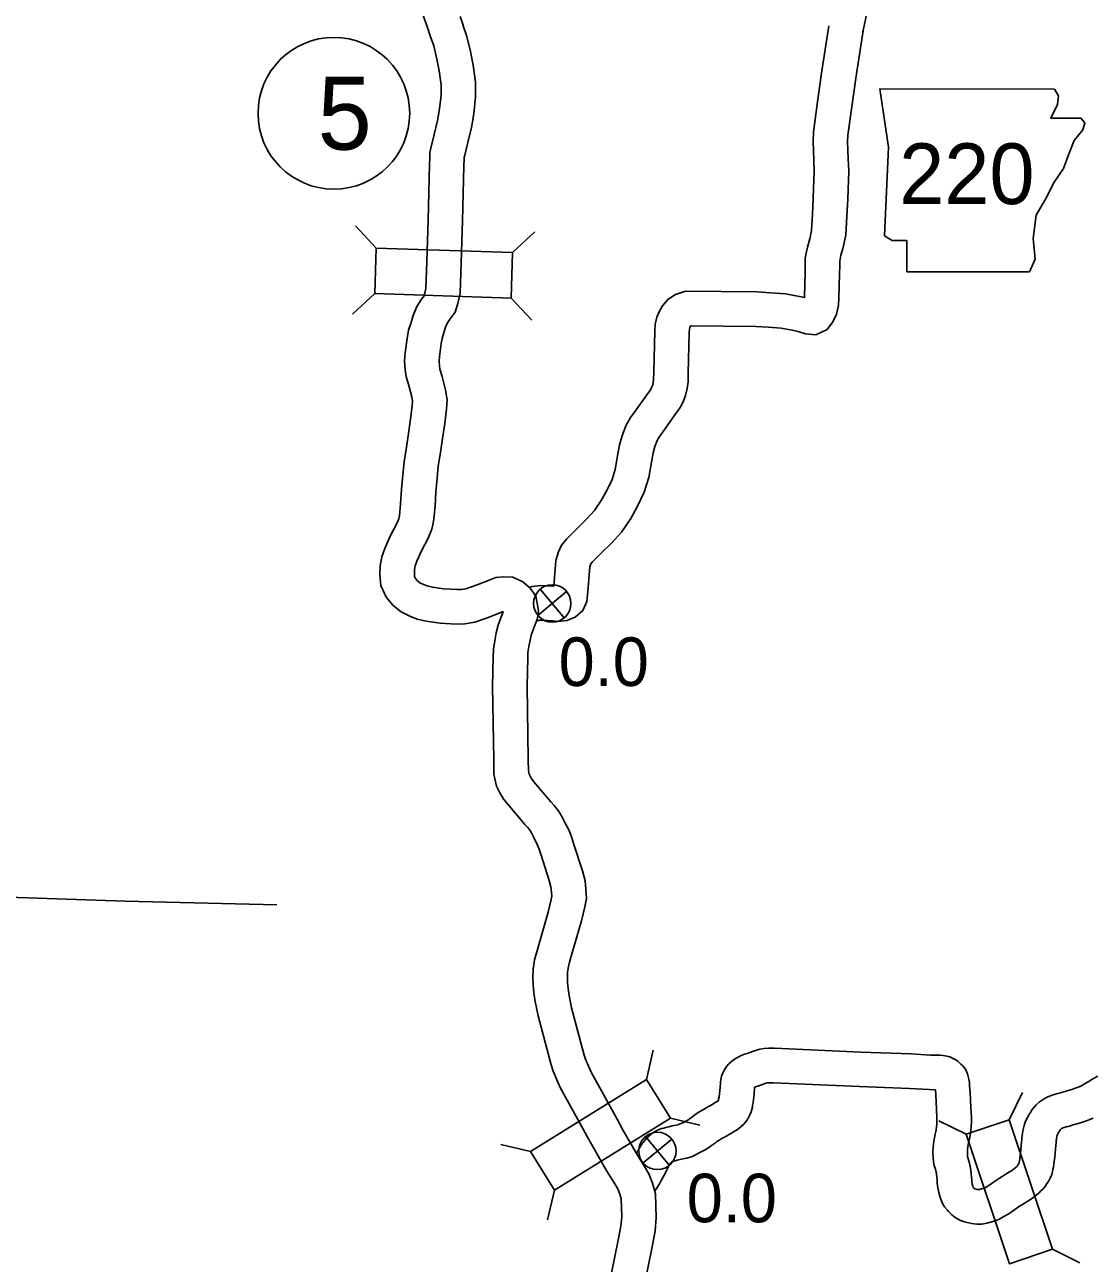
# Model space of a CAD drawing. Extents: x -939622 to -934245, y 1383184 to 1385301.
# Drawn here: x -936434.3 to -936406.41, y 1384683.11 to 1384715.43 of the extents above; entities that cross this region are included whole.
import ezdxf

# ---------------------------------------------------------------- set-up
doc = ezdxf.new("R2010")
doc.units = 0
for name, color, linetype in [('Level 10', 7, 'Continuous'), ('Level 11', 7, 'Continuous'), ('Level 20', 7, 'Continuous'), ('Level 21', 7, 'Continuous'), ('Level 25', 7, 'Continuous'), ('Level 26', 7, 'Continuous'), ('Level 27', 7, 'Continuous'), ('Level 8', 7, 'Continuous')]:
    doc.layers.add(name, color=color, linetype=linetype)

msp = doc.modelspace()

# ---------------------------------------------------------------- linework, layer by layer
at = {"layer": 'Level 10'}
for points in [[(-936422.179, 1384700.936), (-936422.495, 1384700.816), (-936422.788, 1384700.71), (-936422.905, 1384700.689), (-936423.026, 1384700.686), (-936423.365, 1384700.707), (-936423.658, 1384700.75), (-936423.798, 1384700.783), (-936423.891, 1384700.818), (-936423.988, 1384700.867), (-936424.052, 1384700.919), (-936424.099, 1384700.973), (-936424.124, 1384701.031), (-936424.132, 1384701.102), (-936424.127, 1384701.201), (-936424.107, 1384701.308), (-936424.066, 1384701.427), (-936423.947, 1384701.696), (-936423.773, 1384702.032), (-936423.678, 1384702.263), (-936423.631, 1384702.468), (-936423.591, 1384702.861), (-936423.573, 1384703.239), (-936423.535, 1384703.598), (-936423.506, 1384703.912), (-936423.451, 1384704.27), (-936423.394, 1384704.633), (-936423.338, 1384705.024), (-936423.295, 1384705.394), (-936423.273, 1384705.634), (-936423.317, 1384705.905), (-936423.409, 1384706.252), (-936423.462, 1384706.444), (-936423.477, 1384706.53), (-936423.486, 1384706.646), (-936423.474, 1384706.767), (-936423.43, 1384707.113), (-936423.409, 1384707.243), (-936423.359, 1384707.393), (-936423.318, 1384707.534), (-936423.267, 1384707.648), (-936423.2, 1384707.756), (-936423.069, 1384707.929), (-936422.995, 1384708.152), (-936422.932, 1384708.428), (-936422.906, 1384709.217), (-936422.873, 1384710.311), (-936422.839, 1384711.752), (-936422.831, 1384711.931), (-936422.83, 1384711.966), (-936422.825, 1384711.987), (-936422.737, 1384712.356), (-936422.643, 1384712.746), (-936422.581, 1384713.107), (-936422.532, 1384713.546), (-936422.535, 1384713.928), (-936422.595, 1384714.379), (-936422.668, 1384714.731), (-936422.761, 1384715.122), (-936422.862, 1384715.425)], [(-936423.898, 1384715.672), (-936423.785, 1384715.354), (-936423.716, 1384715.144)], [(-936422.933, 1384715.644), (-936422.861, 1384715.423)], [(-936421.859, 1384700.095), (-936422.182, 1384699.972), (-936422.552, 1384699.838), (-936422.812, 1384699.791), (-936423.043, 1384699.785), (-936423.459, 1384699.812), (-936423.826, 1384699.866), (-936424.057, 1384699.92), (-936424.252, 1384699.991), (-936424.48, 1384700.108), (-936424.681, 1384700.27), (-936424.87, 1384700.49), (-936425.003, 1384700.797), (-936425.034, 1384701.073), (-936425.023, 1384701.304), (-936424.98, 1384701.539), (-936424.904, 1384701.758), (-936424.759, 1384702.085), (-936424.59, 1384702.411), (-936424.539, 1384702.536), (-936424.521, 1384702.613), (-936424.489, 1384702.929), (-936424.471, 1384703.308), (-936424.431, 1384703.687), (-936424.399, 1384704.022), (-936424.34, 1384704.408), (-936424.284, 1384704.766), (-936424.231, 1384705.139), (-936424.19, 1384705.489), (-936424.179, 1384705.603), (-936424.198, 1384705.716), (-936424.278, 1384706.016), (-936424.342, 1384706.249), (-936424.371, 1384706.42), (-936424.389, 1384706.658), (-936424.368, 1384706.868), (-936424.321, 1384707.242), (-936424.285, 1384707.461), (-936424.218, 1384707.66), (-936424.166, 1384707.843), (-936424.064, 1384708.073), (-936423.942, 1384708.267), (-936423.877, 1384708.353), (-936423.863, 1384708.395), (-936423.828, 1384708.545), (-936423.806, 1384709.245), (-936423.772, 1384710.336), (-936423.738, 1384711.782), (-936423.731, 1384711.963), (-936423.727, 1384712.095), (-936423.698, 1384712.207), (-936423.612, 1384712.565), (-936423.525, 1384712.927), (-936423.473, 1384713.233), (-936423.433, 1384713.593), (-936423.435, 1384713.865), (-936423.483, 1384714.229), (-936423.547, 1384714.536), (-936423.627, 1384714.876), (-936423.716, 1384715.141)], [(-936422.175, 1384700.938), (-936422.007, 1384701), (-936421.801, 1384701.023), (-936421.562, 1384701.012), (-936421.297, 1384700.892), (-936421.108, 1384700.723), (-936420.963, 1384700.518), (-936420.913, 1384700.291), (-936420.894, 1384700.12), (-936420.928, 1384699.909), (-936420.979, 1384699.775), (-936421.083, 1384699.496), (-936421.112, 1384699.368), (-936421.146, 1384699.202), (-936421.166, 1384699.05), (-936421.173, 1384698.905), (-936421.187, 1384698.168), (-936421.16, 1384696.255), (-936421.155, 1384695.969), (-936421.144, 1384695.91), (-936421.133, 1384695.868), (-936421.102, 1384695.804), (-936421.057, 1384695.728), (-936421.009, 1384695.668), (-936420.564, 1384695.147), (-936420.481, 1384695.053), (-936420.376, 1384694.922), (-936420.292, 1384694.779), (-936420.202, 1384694.613), (-936420.093, 1384694.396), (-936420.023, 1384694.205), (-936419.969, 1384694.036), (-936419.744, 1384693.351), (-936419.675, 1384693.089), (-936419.655, 1384692.868), (-936419.637, 1384692.628), (-936419.683, 1384692.407), (-936419.768, 1384692.044), (-936420.069, 1384691.002), (-936420.107, 1384690.848), (-936420.129, 1384690.699), (-936420.135, 1384690.563), (-936420.132, 1384690.433), (-936420.118, 1384690.273), (-936420.09, 1384690.093), (-936420.026, 1384689.769), (-936419.697, 1384688.539), (-936419.66, 1384688.429), (-936419.585, 1384688.248), (-936419.517, 1384688.093), (-936418.84, 1384686.87), (-936418.677, 1384686.574), (-936418.331, 1384685.973), (-936418.121, 1384685.634), (-936418.011, 1384685.439), (-936417.914, 1384685.199), (-936417.837, 1384684.918), (-936417.818, 1384684.302), (-936417.843, 1384683.952), (-936417.915, 1384683.578), (-936418.64, 1384680.02)], [(-936421.863, 1384700.094), (-936421.814, 1384700.112), (-936421.822, 1384700.09), (-936421.946, 1384699.755), (-936421.992, 1384699.558), (-936422.034, 1384699.352), (-936422.064, 1384699.131), (-936422.072, 1384698.934), (-936422.088, 1384698.17), (-936422.06, 1384696.241), (-936422.054, 1384695.873), (-936422.022, 1384695.711), (-936421.983, 1384695.561), (-936421.898, 1384695.38), (-936421.797, 1384695.211), (-936421.7, 1384695.092), (-936421.244, 1384694.558), (-936421.171, 1384694.474), (-936421.118, 1384694.409), (-936421.075, 1384694.336), (-936421.001, 1384694.198), (-936420.921, 1384694.038), (-936420.874, 1384693.912), (-936420.825, 1384693.757), (-936420.608, 1384693.096), (-936420.565, 1384692.933), (-936420.552, 1384692.793), (-936420.544, 1384692.686), (-936420.562, 1384692.6), (-936420.639, 1384692.272), (-936420.937, 1384691.237), (-936420.991, 1384691.024), (-936421.026, 1384690.783), (-936421.036, 1384690.57), (-936421.031, 1384690.382), (-936421.012, 1384690.165), (-936420.976, 1384689.937), (-936420.903, 1384689.566), (-936420.559, 1384688.28), (-936420.504, 1384688.115), (-936420.413, 1384687.895), (-936420.324, 1384687.692), (-936419.628, 1384686.435), (-936419.462, 1384686.133), (-936419.104, 1384685.511), (-936418.895, 1384685.175), (-936418.823, 1384685.047), (-936418.768, 1384684.91), (-936418.733, 1384684.784), (-936418.719, 1384684.32), (-936418.737, 1384684.069), (-936418.798, 1384683.752), (-936419.513, 1384680.244)], [(-936418.329, 1384685.981), (-936418.292, 1384686.052), (-936418.262, 1384686.103), (-936418.219, 1384686.176), (-936418.17, 1384686.249), (-936418.133, 1384686.295), (-936418.069, 1384686.37), (-936418.003, 1384686.435), (-936417.934, 1384686.491), (-936417.865, 1384686.539), (-936417.786, 1384686.58), (-936417.682, 1384686.619), (-936417.62, 1384686.633), (-936417.544, 1384686.653), (-936417.487, 1384686.667), (-936417.399, 1384686.688), (-936417.248, 1384686.722), (-936417.215, 1384686.731), (-936417.168, 1384686.753), (-936417.108, 1384686.783), (-936416.995, 1384686.844), (-936416.946, 1384686.875), (-936416.905, 1384686.904), (-936416.855, 1384686.942), (-936416.807, 1384686.976), (-936416.751, 1384687.019), (-936416.662, 1384687.075), (-936416.582, 1384687.12), (-936416.539, 1384687.146), (-936416.472, 1384687.186), (-936416.4, 1384687.224), (-936416.355, 1384687.251), (-936416.314, 1384687.273), (-936416.274, 1384687.299), (-936416.224, 1384687.329), (-936416.194, 1384687.349), (-936416.19, 1384687.389), (-936416.175, 1384687.452), (-936416.158, 1384687.608), (-936416.142, 1384687.797), (-936416.137, 1384687.839), (-936416.131, 1384687.893), (-936416.109, 1384687.987), (-936416.078, 1384688.079), (-936416.038, 1384688.157), (-936415.986, 1384688.239), (-936415.918, 1384688.314), (-936415.849, 1384688.375), (-936415.772, 1384688.433), (-936415.699, 1384688.476), (-936415.597, 1384688.53), (-936415.512, 1384688.563), (-936415.439, 1384688.584), (-936415.3, 1384688.634), (-936415.195, 1384688.671), (-936415.109, 1384688.694), (-936414.996, 1384688.71), (-936414.888, 1384688.718), (-936414.733, 1384688.717), (-936412.474, 1384688.618), (-936411.165, 1384688.568), (-936410.652, 1384688.54), (-936410.498, 1384688.533), (-936410.448, 1384688.533), (-936410.395, 1384688.532), (-936410.327, 1384688.527), (-936410.278, 1384688.519), (-936410.186, 1384688.498), (-936410.112, 1384688.471), (-936410.07, 1384688.45), (-936410.015, 1384688.424), (-936409.946, 1384688.38), (-936409.896, 1384688.338), (-936409.86, 1384688.305), (-936409.801, 1384688.245), (-936409.734, 1384688.153), (-936409.69, 1384688.051), (-936409.672, 1384687.982), (-936409.664, 1384687.942), (-936409.659, 1384687.914), (-936409.647, 1384687.862), (-936409.64, 1384687.802)], [(-936406.77, 1384687.713), (-936406.734, 1384687.73), (-936406.684, 1384687.757), (-936406.619, 1384687.795), (-936406.541, 1384687.844), (-936406.417, 1384687.921), (-936406.286, 1384687.989)], [(-936417.857, 1384684.991), (-936417.845, 1384685.005), (-936417.79, 1384685.086), (-936417.735, 1384685.177), (-936417.698, 1384685.244), (-936417.652, 1384685.322), (-936417.609, 1384685.407), (-936417.569, 1384685.486), (-936417.533, 1384685.56), (-936417.504, 1384685.616), (-936417.484, 1384685.65), (-936417.456, 1384685.697), (-936417.444, 1384685.715), (-936417.44, 1384685.721), (-936417.41, 1384685.755), (-936417.407, 1384685.758), (-936417.324, 1384685.78), (-936417.274, 1384685.792), (-936417.194, 1384685.812), (-936417.024, 1384685.849), (-936416.896, 1384685.887), (-936416.777, 1384685.942), (-936416.694, 1384685.984), (-936416.537, 1384686.068), (-936416.444, 1384686.128), (-936416.375, 1384686.176), (-936416.325, 1384686.215), (-936416.273, 1384686.251), (-936416.234, 1384686.281), (-936416.202, 1384686.301), (-936416.127, 1384686.343), (-936416.075, 1384686.375), (-936416.033, 1384686.4), (-936415.959, 1384686.439), (-936415.907, 1384686.47), (-936415.852, 1384686.5), (-936415.797, 1384686.536), (-936415.741, 1384686.57), (-936415.671, 1384686.617), (-936415.597, 1384686.673), (-936415.527, 1384686.738), (-936415.461, 1384686.818), (-936415.429, 1384686.871), (-936415.405, 1384686.91), (-936415.372, 1384686.976), (-936415.339, 1384687.061), (-936415.307, 1384687.182), (-936415.301, 1384687.233), (-936415.285, 1384687.3), (-936415.262, 1384687.522), (-936415.247, 1384687.697), (-936415.224, 1384687.71), (-936415.165, 1384687.726), (-936414.998, 1384687.786), (-936414.929, 1384687.81), (-936414.9, 1384687.814), (-936414.858, 1384687.818), (-936414.756, 1384687.817), (-936412.511, 1384687.718), (-936411.207, 1384687.669), (-936410.695, 1384687.641), (-936410.529, 1384687.634)], [(-936410.529, 1384687.634), (-936410.519, 1384687.506), (-936410.5, 1384687.117), (-936410.489, 1384686.899), (-936410.489, 1384686.801), (-936410.489, 1384686.736), (-936410.496, 1384686.663), (-936410.506, 1384686.588), (-936410.516, 1384686.541), (-936410.531, 1384686.475), (-936410.552, 1384686.39), (-936410.57, 1384686.285), (-936410.587, 1384686.141), (-936410.594, 1384686.005), (-936410.59, 1384685.866), (-936410.575, 1384685.751), (-936410.556, 1384685.655), (-936410.529, 1384685.558), (-936410.507, 1384685.483), (-936410.502, 1384685.46), (-936410.496, 1384685.424), (-936410.489, 1384685.359), (-936410.484, 1384685.285), (-936410.478, 1384685.192), (-936410.464, 1384685.075), (-936410.438, 1384684.955), (-936410.409, 1384684.856), (-936410.387, 1384684.782), (-936410.348, 1384684.68), (-936410.288, 1384684.582), (-936410.223, 1384684.498), (-936410.183, 1384684.452), (-936410.103, 1384684.369), (-936409.987, 1384684.286), (-936409.875, 1384684.225), (-936409.769, 1384684.184), (-936409.587, 1384684.143), (-936409.443, 1384684.126), (-936409.313, 1384684.128), (-936409.181, 1384684.152), (-936409.054, 1384684.185), (-936408.964, 1384684.211), (-936408.868, 1384684.251), (-936408.757, 1384684.313), (-936408.629, 1384684.388), (-936408.527, 1384684.457), (-936408.355, 1384684.577), (-936408.212, 1384684.669), (-936408.128, 1384684.721), (-936408.068, 1384684.756), (-936407.987, 1384684.809), (-936407.894, 1384684.879), (-936407.83, 1384684.937), (-936407.774, 1384684.992), (-936407.722, 1384685.041), (-936407.665, 1384685.109), (-936407.625, 1384685.165), (-936407.592, 1384685.218), (-936407.568, 1384685.253), (-936407.52, 1384685.346), (-936407.492, 1384685.423), (-936407.47, 1384685.504), (-936407.459, 1384685.552), (-936407.446, 1384685.614), (-936407.434, 1384685.697), (-936407.428, 1384685.759), (-936407.414, 1384685.875), (-936407.393, 1384686.085), (-936407.382, 1384686.181), (-936407.374, 1384686.26), (-936407.372, 1384686.305), (-936407.369, 1384686.332), (-936407.365, 1384686.37), (-936407.359, 1384686.401), (-936407.356, 1384686.419), (-936407.35, 1384686.438), (-936407.342, 1384686.465), (-936407.34, 1384686.468), (-936407.331, 1384686.486), (-936407.314, 1384686.514), (-936407.299, 1384686.541), (-936407.284, 1384686.565), (-936407.267, 1384686.59), (-936407.266, 1384686.592), (-936407.261, 1384686.597), (-936407.239, 1384686.618), (-936407.238, 1384686.619), (-936407.17, 1384686.647), (-936407.112, 1384686.665), (-936407.063, 1384686.678), (-936407.003, 1384686.694), (-936406.929, 1384686.715), (-936406.832, 1384686.743), (-936406.743, 1384686.77), (-936406.665, 1384686.794), (-936406.582, 1384686.821), (-936406.492, 1384686.854), (-936406.412, 1384686.888)], [(-936409.64, 1384687.8), (-936409.634, 1384687.744), (-936409.62, 1384687.563), (-936409.601, 1384687.161), (-936409.589, 1384686.921), (-936409.589, 1384686.8), (-936409.59, 1384686.695), (-936409.601, 1384686.564), (-936409.618, 1384686.437), (-936409.636, 1384686.35), (-936409.655, 1384686.268), (-936409.671, 1384686.203), (-936409.679, 1384686.155), (-936409.69, 1384686.065), (-936409.694, 1384685.993), (-936409.692, 1384685.938), (-936409.687, 1384685.898), (-936409.68, 1384685.865), (-936409.663, 1384685.804), (-936409.637, 1384685.715), (-936409.618, 1384685.634), (-936409.603, 1384685.538), (-936409.593, 1384685.438), (-936409.586, 1384685.348), (-936409.581, 1384685.277), (-936409.575, 1384685.222), (-936409.565, 1384685.175), (-936409.547, 1384685.114), (-936409.538, 1384685.083), (-936409.527, 1384685.07), (-936409.518, 1384685.059), (-936409.51, 1384685.051), (-936409.507, 1384685.049), (-936409.501, 1384685.046), (-936409.436, 1384685.031), (-936409.4, 1384685.027), (-936409.375, 1384685.032), (-936409.291, 1384685.053), (-936409.262, 1384685.062), (-936409.26, 1384685.063), (-936409.205, 1384685.093), (-936409.11, 1384685.149), (-936409.035, 1384685.2), (-936408.855, 1384685.325), (-936408.692, 1384685.43), (-936408.593, 1384685.491), (-936408.543, 1384685.521), (-936408.503, 1384685.547), (-936408.469, 1384685.572), (-936408.45, 1384685.59), (-936408.397, 1384685.641), (-936408.378, 1384685.66), (-936408.376, 1384685.661), (-936408.375, 1384685.663), (-936408.347, 1384685.708), (-936408.344, 1384685.719), (-936408.338, 1384685.746), (-936408.332, 1384685.775), (-936408.328, 1384685.803), (-936408.323, 1384685.855), (-936408.308, 1384685.975), (-936408.288, 1384686.179), (-936408.277, 1384686.275), (-936408.272, 1384686.325), (-936408.27, 1384686.382), (-936408.262, 1384686.44), (-936408.256, 1384686.495), (-936408.245, 1384686.563), (-936408.232, 1384686.629), (-936408.212, 1384686.7), (-936408.183, 1384686.787), (-936408.15, 1384686.863), (-936408.116, 1384686.926), (-936408.091, 1384686.968), (-936408.072, 1384687.002), (-936408.046, 1384687.044), (-936407.998, 1384687.118), (-936407.941, 1384687.189), (-936407.893, 1384687.239), (-936407.815, 1384687.312), (-936407.745, 1384687.363), (-936407.666, 1384687.414), (-936407.59, 1384687.447), (-936407.477, 1384687.494), (-936407.365, 1384687.529), (-936407.298, 1384687.547), (-936407.239, 1384687.563), (-936407.176, 1384687.58), (-936407.091, 1384687.605), (-936407.004, 1384687.632), (-936406.936, 1384687.652), (-936406.877, 1384687.672), (-936406.821, 1384687.692), (-936406.762, 1384687.717)]]:
    msp.add_lwpolyline(points, dxfattribs=at)
at = {"layer": 'Level 11'}
for points in [[(-936412.077, 1384721.772), (-936412.077, 1384721.37), (-936412.077, 1384721.024), (-936412.066, 1384720.742), (-936412.048, 1384720.395), (-936412.022, 1384720.031), (-936411.985, 1384719.647), (-936411.934, 1384719.346), (-936411.869, 1384718.973), (-936411.805, 1384718.633), (-936411.745, 1384718.243), (-936411.718, 1384717.982), (-936411.773, 1384717.687), (-936411.874, 1384717.282), (-936411.987, 1384716.906), (-936412.103, 1384716.565), (-936412.214, 1384716.219), (-936412.288, 1384715.863), (-936412.363, 1384715.522), (-936412.423, 1384715.243)], [(-936413.308, 1384715.406), (-936413.498, 1384714.166), (-936413.611, 1384713.354), (-936413.711, 1384712.628), (-936413.719, 1384712.384), (-936413.706, 1384711.898), (-936413.692, 1384711.608), (-936413.716, 1384710.915), (-936413.736, 1384710.485), (-936413.76, 1384710.06), (-936413.778, 1384709.977), (-936413.809, 1384709.841), (-936413.87, 1384709.629), (-936413.925, 1384709.346), (-936413.924, 1384709.157), (-936413.93, 1384708.946), (-936413.946, 1384708.347), (-936413.949, 1384708.31), (-936414.031, 1384708.331), (-936414.439, 1384708.407), (-936414.834, 1384708.436), (-936415.189, 1384708.455), (-936417.056, 1384708.474), (-936417.316, 1384708.39), (-936417.512, 1384708.263), (-936417.656, 1384708.093), (-936417.744, 1384707.938), (-936417.801, 1384707.799), (-936417.844, 1384707.613), (-936417.854, 1384707.442), (-936417.882, 1384706.361), (-936417.886, 1384706.172), (-936417.895, 1384706.09), (-936417.909, 1384706.028), (-936417.936, 1384705.963), (-936417.965, 1384705.905), (-936418.126, 1384705.681), (-936418.382, 1384705.319), (-936418.489, 1384705.176), (-936418.609, 1384704.966), (-936418.709, 1384704.698), (-936418.773, 1384704.462), (-936418.83, 1384704.177), (-936418.888, 1384703.819), (-936418.969, 1384703.561), (-936419.105, 1384703.274), (-936419.251, 1384703.012), (-936419.428, 1384702.751), (-936419.626, 1384702.535), (-936419.889, 1384702.276), (-936420.151, 1384702.016), (-936420.29, 1384701.85), (-936420.372, 1384701.676), (-936420.438, 1384701.445), (-936420.494, 1384700.774), (-936420.837, 1384700.798), (-936421.053, 1384700.772), (-936421.119, 1384700.753)], [(-936412.418, 1384715.27), (-936412.607, 1384714.036), (-936412.72, 1384713.231), (-936412.813, 1384712.551), (-936412.819, 1384712.381), (-936412.807, 1384711.931), (-936412.792, 1384711.615), (-936412.816, 1384710.879), (-936412.837, 1384710.438), (-936412.865, 1384709.939), (-936412.899, 1384709.781), (-936412.937, 1384709.616), (-936412.994, 1384709.419), (-936413.024, 1384709.262), (-936413.023, 1384709.146), (-936413.031, 1384708.919), (-936413.047, 1384708.305), (-936413.06, 1384708.103), (-936413.108, 1384707.874), (-936413.21, 1384707.676), (-936413.356, 1384707.472), (-936413.652, 1384707.338), (-936413.919, 1384707.367), (-936414.088, 1384707.417), (-936414.225, 1384707.452), (-936414.555, 1384707.513), (-936414.89, 1384707.538), (-936415.218, 1384707.555), (-936416.917, 1384707.572), (-936416.933, 1384707.543), (-936416.94, 1384707.526), (-936416.95, 1384707.484), (-936416.955, 1384707.402), (-936416.982, 1384706.34), (-936416.987, 1384706.114), (-936417.006, 1384705.938), (-936417.049, 1384705.753), (-936417.116, 1384705.59), (-936417.193, 1384705.437), (-936417.393, 1384705.159), (-936417.653, 1384704.79), (-936417.735, 1384704.68), (-936417.792, 1384704.582), (-936417.851, 1384704.423), (-936417.897, 1384704.255), (-936417.944, 1384704.017), (-936418.01, 1384703.612), (-936418.128, 1384703.232), (-936418.304, 1384702.862), (-936418.483, 1384702.54), (-936418.72, 1384702.19), (-936418.979, 1384701.91), (-936419.256, 1384701.636), (-936419.488, 1384701.406), (-936419.526, 1384701.36), (-936419.527, 1384701.359), (-936419.548, 1384701.283), (-936419.602, 1384700.641), (-936419.625, 1384700.376), (-936419.73, 1384700.14), (-936419.935, 1384699.968), (-936420.154, 1384699.883), (-936420.37, 1384699.858), (-936420.52, 1384699.873), (-936420.815, 1384699.894), (-936420.874, 1384699.887), (-936420.915, 1384699.875)]]:
    msp.add_lwpolyline(points, dxfattribs=at)
at = {"layer": 'Level 20'}
for p, q in [((-936425.127, 1384709.601), (-936425.668, 1384710.179)), ((-936421.565, 1384709.485), (-936420.987, 1384710.027)), ((-936425.165, 1384708.414), (-936425.743, 1384707.872)), ((-936421.603, 1384708.298), (-936421.062, 1384707.72)), ((-936418.074, 1384687.9), (-936417.893, 1384688.671)), ((-936408.603, 1384686.85), (-936408.25, 1384687.559)), ((-936417.447, 1384686.89), (-936416.676, 1384686.71)), ((-936409.729, 1384686.473), (-936410.438, 1384686.825)), ((-936421.102, 1384686.021), (-936421.873, 1384686.202)), ((-936420.476, 1384685.012), (-936420.657, 1384684.24)), ((-936407.47, 1384683.471), (-936406.761, 1384683.118))]:
    msp.add_line(p, q, dxfattribs=at)
for points in [[(-936425.165, 1384708.414), (-936421.603, 1384708.298), (-936421.565, 1384709.485), (-936425.127, 1384709.601)], [(-936420.476, 1384685.012), (-936417.447, 1384686.89), (-936418.074, 1384687.9), (-936421.102, 1384686.021)], [(-936407.47, 1384683.471), (-936408.603, 1384686.85), (-936409.729, 1384686.473), (-936408.596, 1384683.093)]]:
    msp.add_lwpolyline(points, close=True, dxfattribs=at)
at = {"layer": 'Level 21'}
msp.add_lwpolyline([(-936411.983, 1384713.755), (-936411.755, 1384712.232), (-936411.856, 1384709.923), (-936411.653, 1384709.796), (-936411.273, 1384709.796), (-936411.273, 1384708.984), (-936408.075, 1384708.984), (-936407.923, 1384709.314), (-936407.974, 1384709.847), (-936407.898, 1384710.456), (-936407.618, 1384710.938), (-936407.441, 1384711.293), (-936407.187, 1384711.674), (-936407.035, 1384712.08), (-936406.908, 1384712.41), (-936406.679, 1384712.689), (-936406.629, 1384712.866), (-936406.73, 1384712.993), (-936407.517, 1384712.993), (-936407.339, 1384713.349), (-936407.314, 1384713.577), (-936407.419, 1384713.752)], close=True, dxfattribs=at)
at = {"layer": 'Level 26'}
for p, q in [((-936420.908, 1384700.014), (-936420.156, 1384700.636)), ((-936420.221, 1384699.949), (-936420.843, 1384700.701)), ((-936418.162, 1384685.725), (-936417.409, 1384686.347)), ((-936417.474, 1384685.66), (-936418.097, 1384686.412))]:
    msp.add_line(p, q, dxfattribs=at)
for centre in [(-936420.532, 1384700.325), (-936417.785, 1384686.036)]:
    msp.add_circle(centre, 0.488, dxfattribs=at)
at = {"layer": 'Level 27'}
msp.add_circle((-936426.233, 1384713.12), 1.98, dxfattribs=at)
at = {"layer": 'Level 8'}
msp.add_lwpolyline([(-936427.725, 1384692.461), (-936431.68, 1384692.556), (-936439.584, 1384692.821)], dxfattribs=at)

# ---------------------------------------------------------------- texts
at = {"layer": 'Level 21'}
msp.add_text('220', height=1.584, dxfattribs=at).set_placement((-936411.474, 1384710.75))
at = {"layer": 'Level 25'}
for p in [(-936420.365, 1384698.172), (-936417.021, 1384684.175)]:
    msp.add_text('0.0', height=1.2672, dxfattribs=at).set_placement(p)
at = {"layer": 'Level 27'}
msp.add_text('5', height=1.901, dxfattribs=at).set_placement((-936426.658, 1384712.17))

doc.saveas('drawing.dxf')
